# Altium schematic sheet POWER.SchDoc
size A2; SheetNumber: 3; SheetTotal: 3
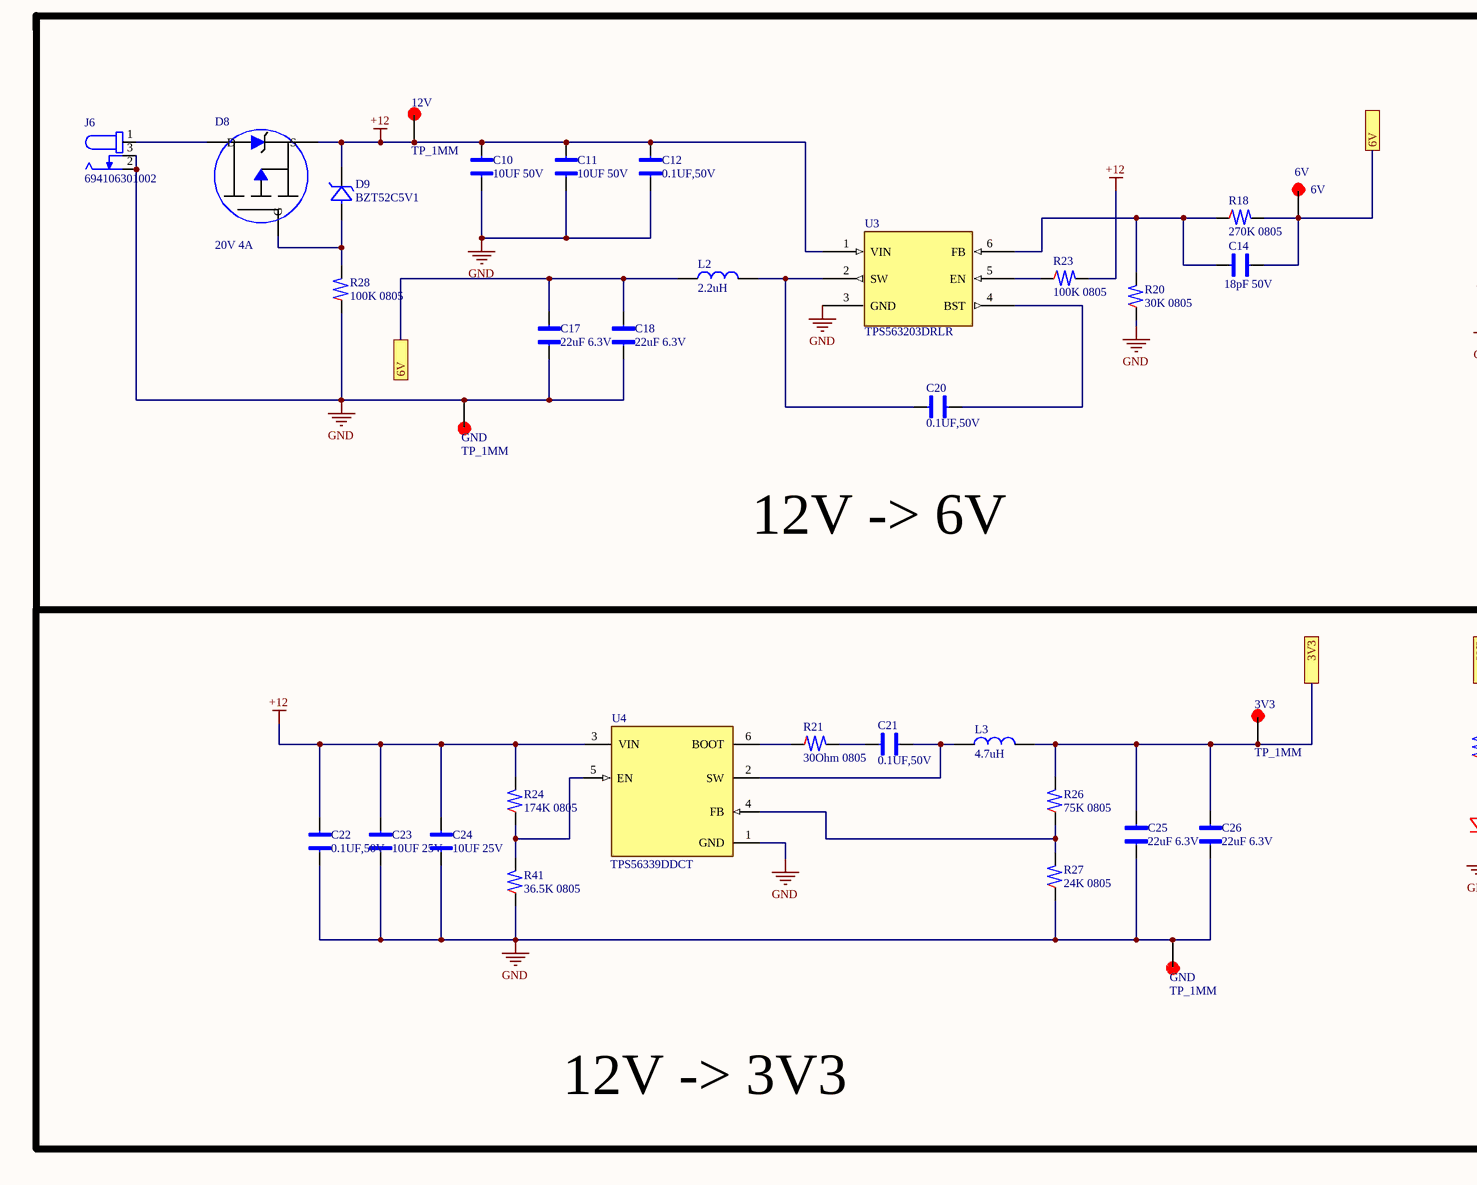
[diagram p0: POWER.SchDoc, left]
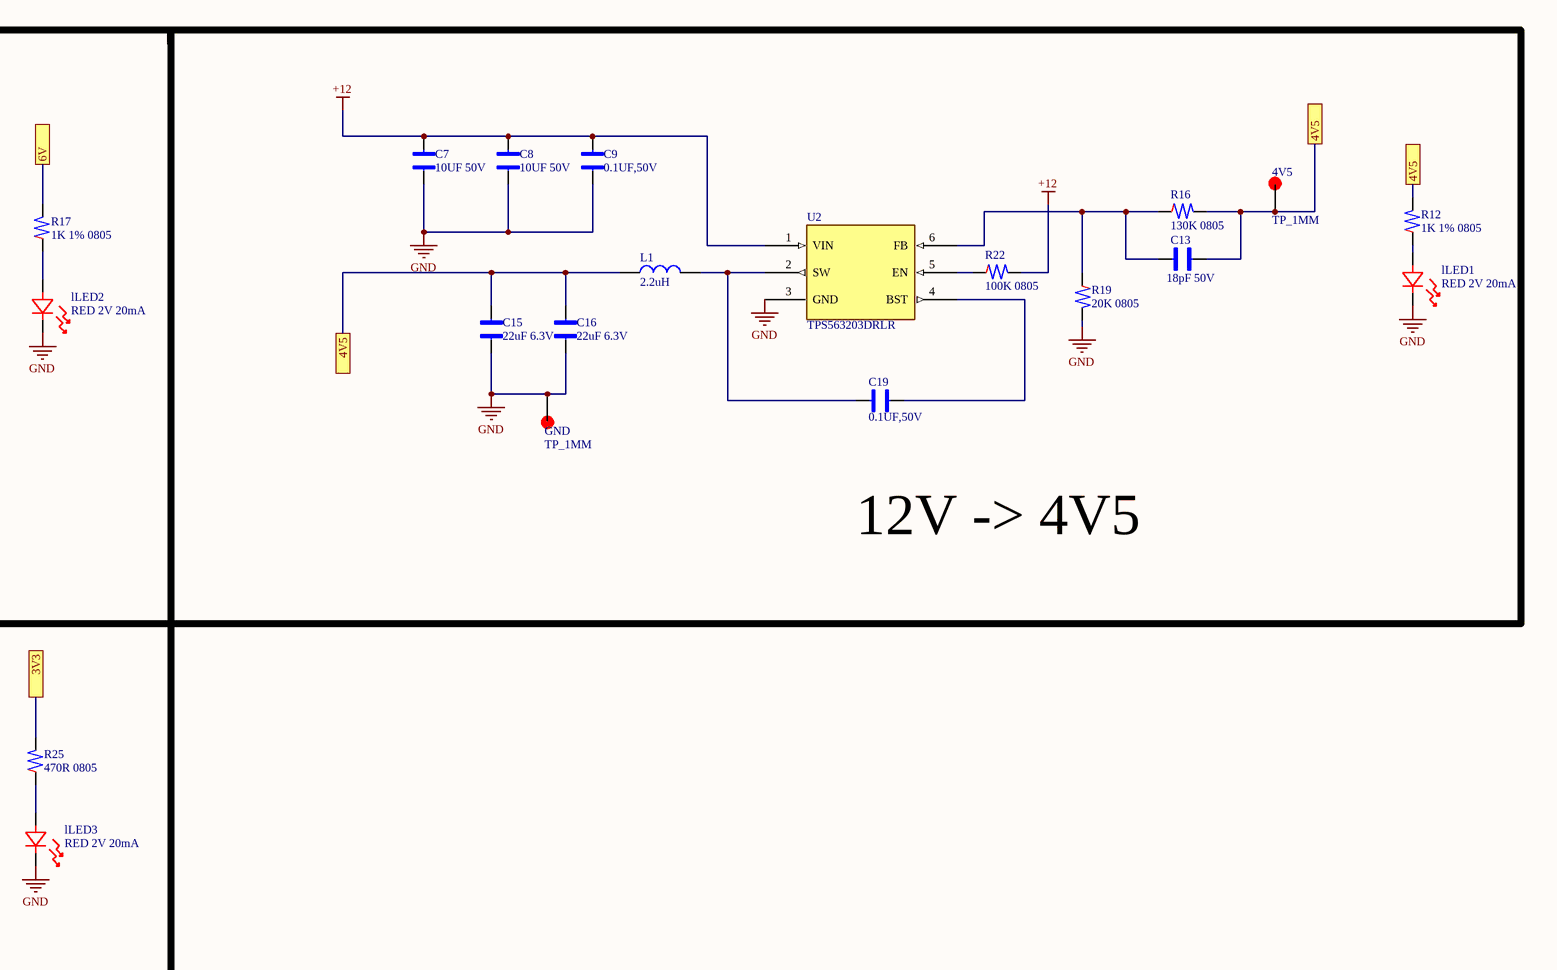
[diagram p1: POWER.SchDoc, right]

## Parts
(Parts that share a designator on the sheet are numbered #1, #2 ... from top to bottom, then left to right.)
3V3  TP_1MM  [TP_1mm]
4V5  TP_1MM  [TP_1mm]
6V  6V  [TP_1mm]
12V  TP_1MM  [TP_1mm]
C7  10UF 50V  [CAP_CER_0805]
C8  10UF 50V  [CAP_CER_0805]
C9  0.1UF,50V  [CAP_CER_0805]
C10  10UF 50V  [CAP_CER_0805]
C11  10UF 50V  [CAP_CER_0805]
C12  0.1UF,50V  [CAP_CER_0805]
C13  18pF 50V  [CAP_CER_0805]
C14  18pF 50V  [CAP_CER_0805]
C15  22uF 6.3V  [CAP_CER_0603]
C16  22uF 6.3V  [CAP_CER_0603]
C17  22uF 6.3V  [CAP_CER_0603]
C18  22uF 6.3V  [CAP_CER_0603]
C19  0.1UF,50V  [CAP_CER_0805]
C20  0.1UF,50V  [CAP_CER_0805]
C21  0.1UF,50V  [CAP_CER_0805]
C22  0.1UF,50V  [CAP_CER_0805]
C23  10UF 25V  [CAP_CER_0805]
C24  10UF 25V  [CAP_CER_0805]
C25  22uF 6.3V  [CAP_CER_0603]
C26  22uF 6.3V  [CAP_CER_0603]
D8  20V 4A  [SOT-23-3]
D9  BZT52C5V1  [SOD-123]
GND#1  TP_1MM  [TP_1mm]
GND#2  TP_1MM  [TP_1mm]
GND#3  TP_1MM  [TP_1mm]
J6  694106301002  [CONN PWR JACK 2.1X5.5MM SOLDER]
L1  2.2uH  [IND_12.5x12.5_H8.5]
L2  2.2uH  [IND_12.5x12.5_H8.5]
L3  4.7uH  [IND_6.8X6.5_H2.8]
lLED1  RED 2V 20mA  [LED_LS R976_AOS]
lLED2  RED 2V 20mA  [LED_LS R976_AOS]
lLED3  RED 2V 20mA  [LED_LS R976_AOS]
R12  1K 1% 0805  [RES_0805]
R16  130K 0805  [RES_0805]
R17  1K 1% 0805  [RES_0805]
R18  270K 0805  [RES_0805]
R19  20K 0805  [RES_0805]
R20  30K 0805  [RES_0805]
R21  30Ohm 0805  [RES_0805]
R22  100K 0805  [RES_0805]
R23  100K 0805  [RES_0805]
R24  174K 0805  [RES_0805]
R25  470R 0805  [RES_0805]
R26  75K 0805  [RES_0805]
R27  24K 0805  [RES_0805]
R28  100K 0805  [RES_0805]
R41  36.5K 0805  [RES_0805]
U2  TPS563203DRLR  [SOT-563]
U3  TPS563203DRLR  [SOT-563]
U4  TPS56339DDCT  [SOT-23-6]

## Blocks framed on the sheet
12V -> 3V3: 3V3 C21-C26 GND#3 L3 lLED3 R21 R24-R27 R41 U4

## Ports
3V3, 4V5, 6V

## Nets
+12: 12V.1 C7.2 C8.2 C9.2 C10.2 C11.2 C12.2 C22.2 C23.2 C24.2 D8.2(S) D9.1(CATHODE) R22.2 R23.2 R24.2 U2.1(VIN) U3.1(VIN) U4.3(VIN)
GND: C7.1 C8.1 C9.1 C10.1 C11.1 C12.1 C15.1 C16.1 C17.1 C18.1 C22.1 C23.1 C24.1 C25.1 C26.1 GND#1.1 GND#2.1 GND#3.1 J6.2 J6.3 lLED1.1 lLED2.1 lLED3.1 R19.2 R20.1 R27.1 R28.1 R41.1 U2.3(GND) U3.3(GND) U4.1(GND)
3V3: 3V3.1 C25.2 C26.2 L3.2 R25.2 R26.2 ; port 3V3
4V5: 4V5.1 C13.2 C15.2 C16.2 L1.1 R12.2 R16.2 ; port 4V5
6V: 6V.1 C14.2 C17.2 C18.2 L2.1 R17.2 R18.2 ; port 6V
NetC13_1: C13.1 R16.1 R19.1 U2.6(FB)
NetC14_1: C14.1 R18.1 R20.2 U3.6(FB)
NetC19_1: C19.1 L1.2 U2.2(SW)
NetC19_2: C19.2 U2.4(BST)
NetC20_1: C20.1 L2.2 U3.2(SW)
NetC20_2: C20.2 U3.4(BST)
NetC21_1: C21.1 L3.1 U4.2(SW)
NetC21_2: C21.2 R21.2
NetD8_1: D8.1(G) D9.2(ANODE) R28.2
NetD8_3: D8.3(D) J6.1
NetlLED1_2: lLED1.2 R12.1
NetlLED2_2: lLED2.2 R17.1
NetlLED3_2: lLED3.2 R25.1
NetR21_1: R21.1 U4.6(BOOT)
NetR22_1: R22.1 U2.5(EN)
NetR23_1: R23.1 U3.5(EN)
NetR24_1: R24.1 R41.2 U4.5(EN)
NetR26_1: R26.1 R27.2 U4.4(FB)

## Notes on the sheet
- 12V -> 6V
- 12V -> 4V5

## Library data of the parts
6V = TP_1MM
C7 C8 C10 C11 = CAP_CER, 0805, X5R, 10UF, 10%, 50V: CAP_CER,0805,X5R,10UF,10%,50V; Manufacturer: Nextgen; Manufacturer Part Number: 0805W106K500CC; LIB MADE BY: MR HOANG
C9 C12 C19-C22 = CAP_CER, 0805, X7R, 0.1UF, 5%, 50V: Ceramic Capacitor, Multilayer, Ceramic, 50V, 10% +Tol, 10% -Tol, X7R, 15% TC, 0.1uF, Surface Mount, 0805; Manufacturer: Nextgen; Manufacturer Part Number: 0805B104K500BD; Capacitance: 100nF; LIB MADE BY: MR HOANG
C13 C14 = CAP_CER, 18PF 50V X8R 0805: Multilayer Ceramic Capacitors MLCC - SMD/SMT 50V 18pF X8R 0805 5%; Manufacturer: Yageo Group; Manufacturer Part Number: C0805C180J5HACTU; Temperature Coefficient: 30ppm/°C; LIB MADE BY: MR HOANG
C15-C18 C25 C26 = CAP_CER 22UF 6.3V X6S 0603: 6.3V 22uF X6S ±20% 0603 Multilayer Ceramic Capacitors MLCC - SMD/SMT ROHS; Manufacturer: Murata; Manufacturer Part Number: GRM188C80J226ME15D; Manufacturer Lifecycle Status: IN PRODUCTION; Capacitance: 22µF; LIB MADE BY: MR HOANG
C23 C24 = CAP_CER, 0805, X5R, 10UF, 10%, 25V: Cap SMD, 0805, X5R, 10UF, 10%, 25V; Manufacturer: Nextgen; Manufacturer Part Number: 0805W106K250CC; LIB MADE BY: MR HOANG
D8 = MOSFET P-CH 20V 4A SOT23-3: P-ch Mosfet 20V 4A 39MΩ@4A, 4.5V 9.1NC@4.5V 294PF@10V SOT-23-3 SMD 2.9MM × 1.3MM × 1.03MM; Manufacturer: Diodes Inc.; Manufacturer Part Number: DMG3415U-7; Drain to Source Breakdown Voltage: -20V; Drain to Source Resistance: 42.5mΩ; Element Configuration: Single; Fall Time: 393ns; Gate to Source Voltage (Vgs): 8V; Input Capacitance: 294pF; Max Junction Temperature (Tj): 150°C; Max Power Dissipation: 900mW; Nominal Vgs: -550mV; Number of Channels: 1; Rds On Max: 39mΩ; Rise Time: 117ns; Turn-Off Delay Time: 795ns; Turn-On Delay Time: 71ns; LIB MADE BY: MR HOANG
D9 = DIODE ZENER 5.1V 500MW SOD123F: BZT52C5V1 Series 500 mW 5.1 V 10 mA Surface Mount Zener Diode - SOD-123; Manufacturer: Diodes Inc.; Manufacturer Part Number: BZT52C5V1-7-F; Current: 1A; Element Configuration: Single; Forward Current: 10mA; Forward Voltage: 900mV; Impedance: 60Ω; Max Junction Temperature (Tj): 150°C; Max Power Dissipation: 370mW; Max Reverse Leakage Current: 2µA; Number of Elements: 1; Output Current: 50mA; Polarity: Unidirectional; Power Rating: 500mW; Reference Voltage: 5.1V; Reverse Standoff Voltage: 2V; Test Current: 5mA; Tolerance: 6%; Voltage Tolerance: 5.88%; LIB MADE BY: MR HOANG
J6 = CONN PWR JACK 2.1X5.5MM SOLDER: DC Power Jack Connector WR-DC, Male, Right Angled, THT, 5 A, 24 V; Manufacturer: Wurth Elektronik; Manufacturer Lifecycle Status: ACTIVE; Current Rating: 5A; Insulation Resistance: 100MΩ; Number of Contacts: 3; Operating Supply Voltage: 24V; Shielding: Unshielded; YEOL: 1 = Estimated lifetime > 10 years; LIB MADE BY: MR HOANG
L1 L2 = FIXED IND 2.2UH 3A 45 MOHM SMD: Inductor Power Shielded Wirewound 2.2uH 20% 100KHz Ferrite 3.1A 0.045Ohm DCR 1515 T/R; Manufacturer: Vishay; Manufacturer Part Number: IFSC1515AHER2R2M01; Current Rating: 3A; DC Resistance (DCR): 45mΩ; Inductance: 2.2µH; Max Current Rating: 2.8A; Number of Circuits: 1; Resistance: 35mΩ; LIB MADE BY: MR HOANG
L3 = FIXED IND 4.7UH 6.3A 33 MOHM SMD: FIXED IND 4.7UH 6.3A 33MOHM SMD / 4.7 µH Shielded Molded Inductor 6.3 A 33mOhm Max Nonstandard; Manufacturer: Sumida; Manufacturer Part Number: 0630CDMCCDS-4R7MC; Core Material: Metal; DC Resistance (DCR): 33mΩ; Inductance: 4.7µH; Number of Circuits: 1; Saturation Current: 6.8A; Test Frequency: 100kHz; Tolerance: 20%
lLED1-lLED3 = LED RED DIFFUSED 0805 SMD: Red 633nm LED Indication - Discrete 2V 0805 (2012 Metric); Manufacturer: Osram; Manufacturer Part Number: LS R976-NR-1-0-20-R18; LIB MADE BY: MR HOANG
R12 R17 = RES_SMD 1K 1% 1/8W 0805: Yageo RC0805FR-071KL SMD Resistor 0603 1k Ohm ±1% Thick Film; Manufacturer: Yageo Group; Max Power Dissipation: 125mW; Resistance: 1kΩ; Temperature Coefficient: 100ppm/°C; Voltage Rating: 150V; LIBRARY MADE BY: Mr. HOANG
R16 = RES_SMD 130K OHM 1% 1/8W 0805: Res Thick Film 0805 130K Ohm 1% 0.125W(1/8W) ±100ppm/C Pad SMD T/R; Manufacturer: Yageo Group; Manufacturer Part Number: RC0805FR-07130KL; Max Power Dissipation: 125mW; Resistance: 130kΩ; Temperature Coefficient: 100ppm/°C; Voltage Rating: 150V; LIB MADE BY: MR HOANG
R18 = RES_SMD 270K OHM 5% 1/8W 0805: Res Thick Film 0805 270K Ohm 5% 0.125W(1/8W) ±100ppm/C Pad SMD T/R; Manufacturer: Yageo Group; Manufacturer Part Number: RC0805JR-07270KL; Manufacturer Package Identifier: 0805 (2012 metric); Max Power Dissipation: 125mW; Resistance: 270kΩ; Temperature Coefficient: 100ppm/°C; Voltage Rating: 150V; LIB MADE BY: MR HOANG
R19 = RES_SMD 20K OHM 1% 1/8W 0805: Res Thick Film 0805 20K Ohm 1% 1/8W ±100ppm/°C Molded SMD Punched Carrier T/R; Manufacturer: Panasonic; Manufacturer Part Number: ERJ6ENF2002V; Manufacturer Lifecycle Status: ACTIVE; Part Series: Precision Thick Film Chip Resistors; Max Power Dissipation: 125mW; Resistance: 20kΩ; Voltage Rating: 150V; LIB MADE BY: MR HOANG
R20 = RES_SMD 30K OHM 1% 1/8W 0805: Res Thick Film 0805 30K Ohm 1% 0.125W ±100ppm/°C Molded SMD Paper T/R; Manufacturer: Stackpole Electronics; Manufacturer Part Number: RMCF0805FT30K0; Manufacturer Package Identifier: 0805 (2012 metric); Max Power Dissipation: 125mW; Resistance: 30kΩ; Voltage Rating: 150V; LIB MADE BY: MR HOANG
R21 = RES_SMD 30 OHM 1% 1/8W 0805: Res Thick Film 0805 30 Ohm 1% 0.125W(1/8W) ±100ppm/C Pad SMD T/R; Manufacturer: Yageo Group; Manufacturer Part Number: RC0805FR-0730RL; Manufacturer Package Identifier: 0805 (2012 metric); Max Power Dissipation: 125mW; Resistance: 30Ω; Temperature Coefficient: 100ppm/°C; Voltage Rating: 150V; LIB MADE BY: MR HOANG
R22 R23 R28 = RES_SMD 100K 1% 1/8W 0805: 125mW Thick Film Resistors 150V ±100ppm/℃ ±1% 100kΩ 0805 Chip Resistor - Surface Mount ROHS; Manufacturer: Yageo Group; Manufacturer Part Number: RC0805FR-07100KL; Temperature Coefficient: 100ppm/°C; LIB MADE BY: MR HOANG
R24 = RES_SMD 174K OHM 1% 1/8W 0805: Res Thick Film 0805 174K Ohm 1% 0.125W(1/8W) ±100ppm/C Pad SMD T/R Automotive AEC-Q200; Manufacturer: Vishay; Manufacturer Part Number: CRCW0805174KFKEA; Manufacturer Package Identifier: CRCW0805-e3; Max Power Dissipation: 125mW; Resistance: 174kΩ; Temperature Coefficient: 100ppm/°C; Voltage Rating: 150V; LIB MADE BY: MR HOANG
R25 = RES_SMD 470 OHM 5% 1/8W 0805: Res Thick Film 0805 470 Ohm 5% 0.125W(1/8W) ±100ppm/C Pad SMD T/R Automotive AEC-Q200; Manufacturer: TE Connectivity; Manufacturer Part Number: CRGCQ0805J470R; Manufacturer Lifecycle Status: ACTIVE; Operating Supply Voltage: 150V; Power Rating: 125mW; Resistance: 470Ω; Temperature Coefficient: 100ppm/°C
R26 = RES_SMD 75K OHM 1% 1/8W 0805: Res Thick Film 0805 75K Ohm 1% 1/8W ±100ppm/°C Molded SMD SMD Paper Tape on Plastic Reel; Manufacturer: Bourns; Manufacturer Part Number: CR0805-FX-7502ELF; Power Rating: 125mW; Resistance: 75kΩ; Voltage Rating: 150V; LIB MADE BY: MR HOANG
R27 = RES_SMD 24K OHM 1% 1/8W 0805: Res Thick Film 0805 24K Ohm 1% 0.125W(1/8W) ±100ppm/C Pad SMD T/R; Manufacturer: Yageo Group; Manufacturer Part Number: RC0805FR-0724KL; Manufacturer Package Identifier: 0805 (2012 metric); Power Rating: 125mW; Resistance: 24kΩ; Temperature Coefficient: 100ppm/°C; Voltage Rating: 150V; LIB MADE BY: MR HOANG
R41 = RES_SMD 36.5K OHM 1% 1/8W 0805: Res Thick Film 0805 36.5K Ohm 1% 0.125W ±100ppm/°C Molded SMD Paper T/R; Manufacturer: Stackpole Electronics; Manufacturer Part Number: RMCF0805FT36K5; Manufacturer Package Identifier: 0805 (2012 metric); Max Power Dissipation: 125mW; Resistance: 36.5kΩ; Voltage Rating: 150V; LIB MADE BY: MR HOANG
U2 U3 = IC REG BUCK ADJ 3A SOT563_1: 4.2-V to 17-V input, 3-A synchronous buck converter in SOT563 6-SOT-5X3 -40 to 125; Manufacturer: Texas Instruments; Manufacturer Lifecycle Status: ACTIVE; LIB MADE BY: MR HOANG
U4 = IC REG BUCK ADJ 3A SOT23: 4.5-V to 24-V input, 3-A output synchronous buck converter 6-SOT-23-THIN -40 to 125; Manufacturer: Texas Instruments; Manufacturer Lifecycle Status: ACTIVE; LIB MADE BY: MR HOANG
